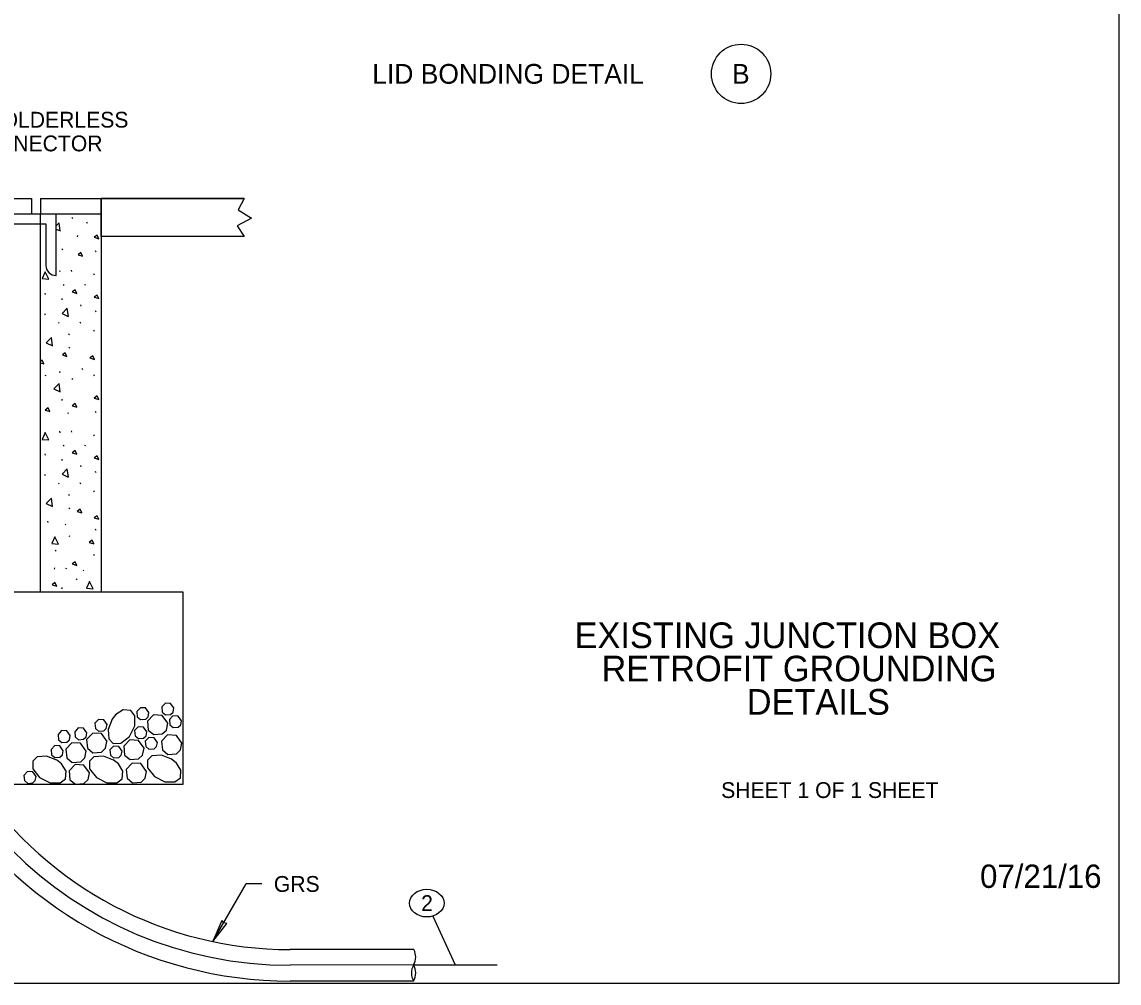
# Model space of a CAD drawing. Extents: x 99862 to 103151, y 100000 to 102076.
# Drawn here: x 102040 to 103151, y 100000 to 100972 of the extents above; entities that cross this region are included whole.
import ezdxf

# ---------------------------------------------------------------- set-up
doc = ezdxf.new("R2010")
doc.units = 0
for name, color, linetype in [('Level 1', 7, 'Continuous'), ('Level 11', 7, 'Continuous'), ('Level 12', 7, 'Continuous'), ('Level 13', 7, 'Continuous'), ('Level 14', 7, 'Continuous'), ('Level 15', 7, 'Continuous'), ('Level 16', 7, 'Continuous'), ('Level 2', 7, 'Continuous'), ('Level 20', 7, 'Continuous'), ('Level 3', 7, 'Continuous'), ('Level 6', 7, 'Continuous'), ('Level 62', 7, 'Continuous')]:
    doc.layers.add(name, color=color, linetype=linetype)

msp = doc.modelspace()

# ---------------------------------------------------------------- linework, layer by layer
at = {"layer": 'Level 1'}
for p, q in [((102059.1, 100395.5), (102059.1, 100778)), ((102059.1, 100778), (102120.6, 100778)), ((102120.6, 100778), (102120.6, 100395.5))]:
    msp.add_line(p, q, dxfattribs=at)
msp.add_lwpolyline([(99862, 99999.5), (103151, 99999.5), (103151, 102075.5), (99862, 102075.5)], close=True, dxfattribs=at)
at = {"layer": 'Level 11'}
for points in [[(100996.7, 100395.5), (102203.1, 100395.5), (102203.1, 100200.5), (100996.7, 100200.5)], [(102168.9, 100273.2), (102165.6, 100277.9), (102160.3, 100278.2), (102156.6, 100274.4), (102157.1, 100269), (102160.4, 100266.3), (102165.7, 100266.7), (102168.1, 100269.1), (102168.9, 100273.2)], [(102194.2, 100277.9), (102190.9, 100282.6), (102185.6, 100282.9), (102181.9, 100279.1), (102182.4, 100273.7), (102185.7, 100271), (102190.9, 100271.4), (102193.4, 100273.8), (102194.2, 100277.9)], [(102126.5, 100261.3), (102123.2, 100266), (102117.9, 100266.3), (102114.2, 100262.5), (102114.7, 100257.1), (102118, 100254.4), (102123.2, 100254.8), (102125.7, 100257.2), (102126.5, 100261.3)], [(102131.7, 100266.5), (102127.6, 100256.2), (102128.4, 100246.6), (102132.7, 100242.1), (102140.5, 100242.2), (102149.3, 100249.1), (102154.6, 100259.7), (102154.7, 100269.8), (102150.7, 100275.4), (102142.8, 100275.9), (102135.6, 100271.4), (102131.5, 100266.1)], [(102188, 100262.5), (102182.4, 100270.4), (102173.6, 100270.9), (102167.4, 100264.5), (102168.3, 100255.6), (102173.8, 100251), (102182.5, 100251.7), (102186.6, 100255.6), (102188, 100262.5)], [(102201.9, 100264.9), (102198.6, 100269.7), (102193.3, 100270), (102189.6, 100266.1), (102190.1, 100260.8), (102193.4, 100258), (102198.7, 100258.4), (102201.1, 100260.8), (102201.9, 100264.9)], [(102089.3, 100249.9), (102086, 100254.7), (102080.6, 100255), (102077, 100251.1), (102077.5, 100245.8), (102080.8, 100243), (102086, 100243.4), (102088.5, 100245.8), (102089.3, 100249.9)], [(102106.1, 100252.7), (102102.8, 100257.5), (102097.4, 100257.8), (102093.8, 100253.9), (102094.3, 100248.6), (102097.6, 100245.8), (102102.8, 100246.2), (102105.3, 100248.6), (102106.1, 100252.7)], [(102166.8, 100253.9), (102163.4, 100258.6), (102158.1, 100258.9), (102154.4, 100255.1), (102155, 100249.7), (102158.3, 100247), (102163.5, 100247.4), (102166, 100249.7), (102166.8, 100253.9)], [(102126.5, 100244.1), (102120.9, 100252), (102112.1, 100252.5), (102105.9, 100246.1), (102106.8, 100237.2), (102112.3, 100232.6), (102121, 100233.3), (102125.1, 100237.3), (102126.4, 100244.1)], [(102164, 100237.1), (102158.4, 100245), (102149.6, 100245.5), (102143.4, 100239.1), (102144.3, 100230.2), (102149.8, 100225.6), (102158.5, 100226.3), (102162.6, 100230.3), (102164, 100237.1)], [(102177.5, 100243.1), (102174.1, 100247.8), (102168.8, 100248.1), (102165.1, 100244.3), (102165.7, 100238.9), (102168.9, 100236.2), (102174.2, 100236.6), (102176.7, 100239), (102177.5, 100243.1)], [(102202.4, 100242.4), (102196.8, 100250.2), (102187.9, 100250.7), (102181.8, 100244.4), (102182.7, 100235.4), (102188.2, 100230.9), (102196.9, 100231.5), (102201, 100235.5), (102202.3, 100242.3)], [(102082.2, 100234.7), (102078.9, 100239.5), (102073.6, 100239.8), (102069.9, 100235.9), (102070.4, 100230.6), (102073.7, 100227.8), (102078.9, 100228.2), (102081.4, 100230.6), (102082.2, 100234.7)], [(102105.4, 100234.3), (102099.8, 100242.2), (102091, 100242.7), (102084.8, 100236.3), (102085.7, 100227.4), (102091.2, 100222.8), (102099.9, 100223.4), (102104, 100227.4), (102105.3, 100234.3)], [(102141.7, 100234.2), (102138.4, 100238.9), (102133.1, 100239.2), (102129.4, 100235.4), (102129.9, 100230), (102133.2, 100227.3), (102138.5, 100227.7), (102140.9, 100230.1), (102141.7, 100234.2)], [(102075.7, 100225.2), (102065.4, 100229.3), (102055.8, 100228.5), (102051.3, 100224.2), (102051.5, 100216.4), (102058.3, 100207.6), (102068.9, 100202.3), (102079, 100202.1), (102084.6, 100206.2), (102085.1, 100214.1), (102080.6, 100221.3), (102075.3, 100225.4)], [(102133.1, 100225.2), (102122.8, 100229.3), (102113.2, 100228.5), (102108.7, 100224.1), (102108.8, 100216.4), (102115.7, 100207.6), (102126.4, 100202.3), (102136.4, 100202.1), (102142, 100206.1), (102142.5, 100214.1), (102138, 100221.3), (102132.7, 100225.4)], [(102166.4, 100213.7), (102160.9, 100221.6), (102152, 100222.1), (102145.9, 100215.7), (102146.8, 100206.7), (102152.2, 100202.2), (102161, 100202.8), (102165.1, 100206.8), (102166.4, 100213.7)], [(102191.9, 100226.1), (102181.6, 100230.2), (102172, 100229.4), (102167.5, 100225.1), (102167.6, 100217.4), (102174.5, 100208.6), (102185.1, 100203.3), (102195.1, 100203.1), (102200.8, 100207.1), (102201.3, 100215.1), (102196.7, 100222.2), (102191.5, 100226.4)], [(102054.7, 100208.5), (102051.4, 100213.3), (102046, 100213.6), (102042.3, 100209.7), (102042.9, 100204.4), (102046.2, 100201.6), (102051.4, 100202), (102053.9, 100204.4), (102054.7, 100208.5)], [(102108.7, 100212.2), (102103.1, 100220.1), (102094.3, 100220.6), (102088.1, 100214.2), (102089, 100205.3), (102094.5, 100200.7), (102103.2, 100201.4), (102107.3, 100205.4), (102108.7, 100212.2)]]:
    msp.add_lwpolyline(points, dxfattribs=at)
at = {"layer": 'Level 12'}
for q in [(102311.9, 100017.5), (102521.3, 100017.9)]:
    msp.add_line((102436.8, 100017.9), q, dxfattribs=at)
msp.add_arc((102311.9, 100415.9), 398.4, 180, 270, dxfattribs=at)
at = {"layer": 'Level 13'}
for p, q in [((102437.2, 100033.4), (102311.9, 100033.4)), ((102436.8, 100001.5), (102311.9, 100001.5))]:
    msp.add_line(p, q, dxfattribs=at)
for radius, start in [(414.4, 211.3198), (382.5, 214.2727)]:
    msp.add_arc((102311.9, 100415.9), radius, start, 270, dxfattribs=at)
at = {"layer": 'Level 14'}
for p, q in [((102092, 100772.9), (102091.4, 100774.2)), ((102106.6, 100768.3), (102106, 100769.6)), ((102096.5, 100756.2), (102096.4, 100754.9)), ((102081.5, 100742.5), (102080.9, 100741.6)), ((102115.4, 100739.3), (102114.8, 100740.6)), ((102079.2, 100719.2), (102078.6, 100720.5)), ((102091, 100719.7), (102090.4, 100721)), ((102113.9, 100715.8), (102113.3, 100717.2)), ((102082.7, 100706.4), (102082.2, 100705.6)), ((102104.4, 100706.5), (102103.9, 100705.6)), ((102064.4, 100696.5), (102063.8, 100697.9)), ((102080.8, 100692.4), (102080.7, 100691.1)), ((102064.2, 100675.4), (102063.6, 100676.7)), ((102100.5, 100684.6), (102099.9, 100686)), ((102115.4, 100678.6), (102114.8, 100679.9)), ((102078.1, 100668.2), (102077.5, 100667.3)), ((102099.9, 100667), (102099.3, 100668.3)), ((102088.2, 100656.6), (102087.6, 100655.7)), ((102113.9, 100659.1), (102113.3, 100660.4)), ((102088.5, 100643), (102087.9, 100642.2)), ((102102.1, 100620.2), (102101.5, 100621.6)), ((102064.4, 100614.6), (102063.8, 100613.7)), ((102079.2, 100617.2), (102078.6, 100618.5)), ((102092, 100610.2), (102091.4, 100611.5)), ((102113.9, 100613.8), (102113.3, 100615.1)), ((102080.8, 100590.4), (102080.7, 100589.1)), ((102115.4, 100576.6), (102114.8, 100577.9)), ((102087.3, 100576.6), (102086.7, 100575.7)), ((102079.2, 100556.5), (102078.6, 100557.9)), ((102091, 100557), (102090.4, 100558.3)), ((102082.7, 100543.8), (102082.2, 100542.9)), ((102104.4, 100543.8), (102103.9, 100542.9)), ((102113.9, 100553.2), (102113.3, 100554.5)), ((102064.4, 100533.9), (102063.8, 100535.2)), ((102080.8, 100529.7), (102080.7, 100528.4)), ((102100.5, 100522), (102099.9, 100523.3)), ((102064.2, 100512.8), (102063.6, 100514.1)), ((102115.4, 100516), (102114.8, 100517.3)), ((102078.1, 100505.6), (102077.5, 100504.7)), ((102099.9, 100504.3), (102099.3, 100505.7)), ((102088.2, 100493.9), (102087.6, 100493.1)), ((102113.9, 100496.5), (102113.3, 100497.8)), ((102088.5, 100480.4), (102087.9, 100479.5)), ((102067.1, 100465.5), (102066.5, 100466.9)), ((102084.7, 100464), (102084.2, 100463.1)), ((102115.4, 100457.4), (102114.8, 100458.8)), ((102088.4, 100452.3), (102088.2, 100451)), ((102074.6, 100437.6), (102074, 100436.7)), ((102113.9, 100431.9), (102113.3, 100433.2)), ((102073.2, 100419.7), (102073, 100418.4)), ((102085.3, 100419.4), (102084.7, 100418.5)), ((102103, 100417.5), (102102.4, 100416.7)), ((102080.8, 100399.7), (102080.7, 100398.4)), ((102095.9, 100408.5), (102095.3, 100407.7))]:
    msp.add_line(p, q, dxfattribs=at)
for points in [[(102079.2, 100760.6), (102078, 100769), (102075, 100765.9)], [(102075, 100762.5), (102079, 100760.7)], [(102118.3, 100752.8), (102116.5, 100756.5), (102113.6, 100754.3), (102118.3, 100752.8)], [(102101.8, 100735.2), (102100.1, 100738.9), (102097.2, 100736.7), (102101.8, 100735.2)], [(102067.7, 100711.9), (102063.8, 100719.4), (102060.7, 100712.5), (102067.6, 100711.9)], [(102095.9, 100697.5), (102094.2, 100701.2), (102091.2, 100699), (102095.9, 100697.5)], [(102118.3, 100692.2), (102116.5, 100695.8), (102113.6, 100693.6), (102118.3, 100692.2)], [(102087.4, 100674.1), (102086.3, 100682.4), (102081, 100677), (102087.3, 100674.1)], [(102071.4, 100644.5), (102070.2, 100652.9), (102065, 100647.5), (102071.3, 100644.6)], [(102086, 100633.7), (102084.2, 100637.4), (102081.3, 100635.2), (102086, 100633.7)], [(102113.9, 100630.7), (102112.1, 100634.3), (102109.2, 100632.2), (102113.9, 100630.7)], [(102062.5, 100626.2), (102060.7, 100629.8), (102059.1, 100628.7)], [(102059.1, 100627.2), (102062.5, 100626.2)], [(102079.2, 100598), (102078, 100606.3), (102072.8, 100600.9), (102079, 100598)], [(102118.3, 100590.2), (102116.5, 100593.8), (102113.6, 100591.6), (102118.3, 100590.2)], [(102068.6, 100577.9), (102066.8, 100581.6), (102063.9, 100579.4), (102068.6, 100577.9)], [(102096.1, 100582.4), (102094.3, 100586), (102091.4, 100583.8), (102096.1, 100582.4)], [(102067.7, 100549.2), (102063.8, 100556.7), (102060.7, 100549.8), (102067.6, 100549.2)], [(102095.9, 100534.9), (102094.2, 100538.5), (102091.2, 100536.3), (102095.9, 100534.9)], [(102118.3, 100529.5), (102116.5, 100533.2), (102113.6, 100531), (102118.3, 100529.5)], [(102087.4, 100511.4), (102086.3, 100519.8), (102081, 100514.4), (102087.3, 100511.5)], [(102071.4, 100481.8), (102070.2, 100490.2), (102065, 100484.8), (102071.3, 100481.9)], [(102101.1, 100475.3), (102099.4, 100479), (102096.4, 100476.8), (102101.1, 100475.3)], [(102118.3, 100468.9), (102116.5, 100472.5), (102113.6, 100470.3), (102118.3, 100468.9)], [(102077.5, 100443.8), (102073.6, 100451.2), (102070.5, 100444.3), (102077.4, 100443.8)], [(102113.3, 100443.9), (102111.5, 100447.6), (102108.6, 100445.4), (102113.3, 100443.9)], [(102095.9, 100422.2), (102094.2, 100425.9), (102091.2, 100423.7), (102095.9, 100422.2)], [(102075.6, 100401.2), (102073.8, 100404.9), (102070.9, 100402.7), (102075.6, 100401.2)], [(102112.6, 100398.4), (102108.7, 100405.9), (102105.6, 100399), (102112.5, 100398.4)]]:
    msp.add_lwpolyline(points, dxfattribs=at)
at = {"layer": 'Level 15'}
for p, q in [((102233.7, 100041.5), (102267.4, 100099.8)), ((102283.4, 100099.8), (102267.4, 100099.8)), ((102456.3, 100067.3), (102479, 100017.9))]:
    msp.add_line(p, q, dxfattribs=at)
msp.add_lwpolyline([(102233.7, 100041.5), (102247.7, 100059.8), (102244.6, 100060.3), (102242.6, 100062.7)], close=True, dxfattribs=at)
for centre, start, end in [((102422.7, 100026), 330, 26.9934), ((102451, 100009.7), 150, 210), ((102422.7, 100009.7), 330, 30)]:
    msp.add_arc(centre, 16.3, start, end, dxfattribs=at)
at = {"layer": 'Level 16'}
for p, q in [((102265.2, 100793.5), (102120.6, 100793.5)), ((102265.2, 100755.1), (102120.6, 100755.1))]:
    msp.add_line(p, q, dxfattribs=at)
msp.add_lwpolyline([(102265.2, 100793.5), (102259.2, 100782.1), (102272.8, 100773.8), (102258.4, 100765.8), (102265.2, 100755.1)], dxfattribs=at)
at = {"layer": 'Level 2'}
for p, q in [((102075, 100715.7), (102075, 100778)), ((102022.7, 100767.8), (102064.6, 100767.8)), ((102064.6, 100767.8), (102064.6, 100725.9))]:
    msp.add_line(p, q, dxfattribs=at)
msp.add_arc((102074.8, 100725.9), 10.2, 180, 271.1655, dxfattribs=at)
at = {"layer": 'Level 20'}
msp.add_circle((102768.4, 100919.7), 30, dxfattribs=at)
msp.add_ellipse((102450.2, 100080.4), major_axis=(-17.5, 0), ratio=0.8, dxfattribs=at)
at = {"layer": 'Level 3'}
for p, q in [((101146, 100793.5), (102050.1, 100793.5)), ((102050.1, 100793.5), (102050.1, 100778)), ((102059.1, 100793.5), (102059.1, 100778)), ((102059.1, 100793.5), (102120.6, 100793.5)), ((102120.6, 100793.5), (102120.6, 100778)), ((101079.2, 100778), (102059.1, 100778))]:
    msp.add_line(p, q, dxfattribs=at)
at = {"layer": 'Level 6'}
msp.add_lwpolyline([(102120.6, 100755.1), (102120.6, 100793.5), (102265.2, 100793.5), (102259.2, 100782.1), (102272.8, 100773.8), (102258.4, 100765.8), (102265.2, 100755.1)], close=True, dxfattribs=at)

# ---------------------------------------------------------------- texts
at = {"layer": 'Level 15'}
msp.add_text('07/21/16', height=23.62, dxfattribs=at).set_placement((103010.3, 100095.8))
at = {"layer": 'Level 20'}
for s, height, p in [(' LID BONDING DETAIL', 20, (102387.6, 100909.7)), ('B', 20, (102759.2, 100909.7)), ('2', 16, (102444.5, 100072.4))]:
    msp.add_text(s, height=height, dxfattribs=at).set_placement(p)
for s, p in [('COPPER SOLDERLESS', (101909.2, 100865.3)), ('CRIMP CONNECTOR', (101909.2, 100841.3)), ('GRS', (102295.4, 100091.8))]:
    msp.add_text(s, height=16, rotation=360, dxfattribs=at).set_placement(p)
at = {"layer": 'Level 62'}
for s, height, p in [('EXISTING JUNCTION BOX', 26, (102599.8, 100338.5)), ('RETROFIT GROUNDING', 26, (102627.1, 100304.8)), ('DETAILS', 26, (102774.1, 100271.1)), ('SHEET 1 OF 1 SHEET', 16, (102748.2, 100186.8))]:
    msp.add_text(s, height=height, dxfattribs=at).set_placement(p)

doc.saveas('drawing.dxf')
